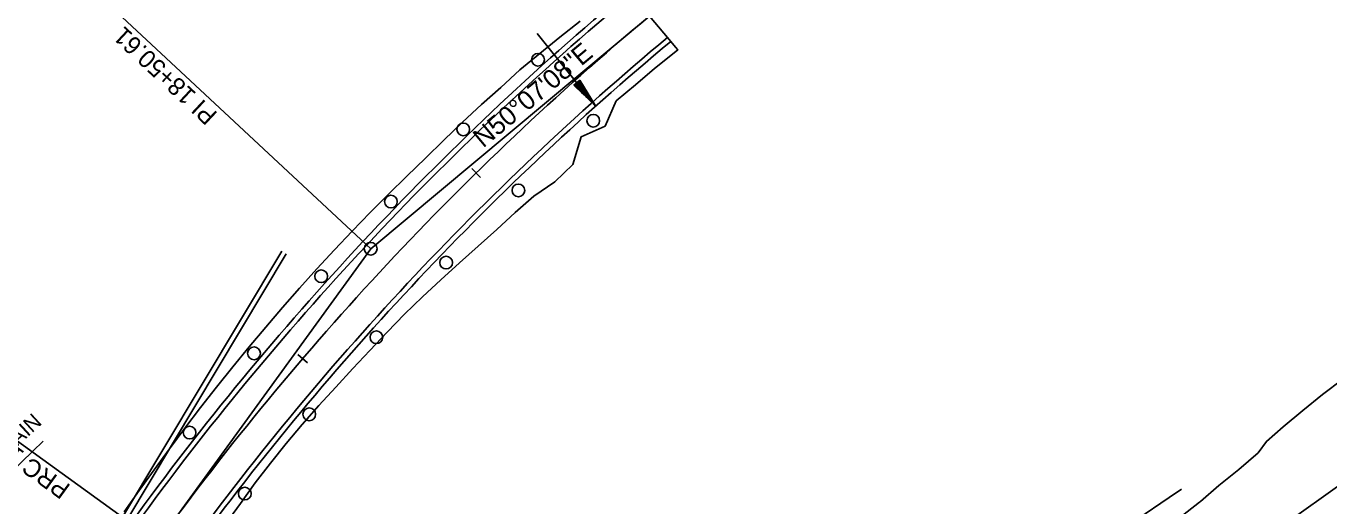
# Model space of a CAD drawing. Extents: x 1300404 to 1323571, y 234004 to 252077.
# Drawn here: x 1311569 to 1312081, y 242253 to 242442 of the extents above; entities that cross this region are included whole.
import ezdxf

# ---------------------------------------------------------------- set-up
doc = ezdxf.new("R2010")
doc.units = 0
for name, color, linetype in [('R_Const Limits', 7, 'Continuous'), ('R_Flow Arrows', 7, 'Continuous'), ('R_MOT Proposed', 7, 'Continuous'), ('R_No Plot', 7, 'Continuous'), ('R_Shoulder', 7, 'Continuous')]:
    doc.layers.add(name, color=color, linetype=linetype)

msp = doc.modelspace()

# ---------------------------------------------------------------- linework, layer by layer
at = {"layer": 'R_Const Limits'}
for points in [[(1312056.31, 242278.46), (1312056.31, 242278.46), (1312062.86, 242284.21), (1312070.55, 242290.61), (1312078.32, 242296.91), (1312086.32, 242302.96)], [(1312022.18, 242248.4), (1312030.07, 242254.56), (1312030.44, 242254.85), (1312037.66, 242261.15), (1312045.44, 242267.46), (1312053.09, 242273.96), (1312056.31, 242278.46), (1312056.31, 242278.46), (1312056.31, 242278.46)]]:
    msp.add_lwpolyline(points, dxfattribs=at)
at = {"layer": 'R_Flow Arrows'}
for p, q in [((1311786.49, 242420.52), (1311784.14, 242418.59)), ((1311784.14, 242418.59), (1311792.75, 242410.46)), ((1311786.49, 242420.52), (1311792.75, 242410.46))]:
    msp.add_line(p, q, dxfattribs=at)
for points in [[(1311769.83, 242438.85), (1311773.45, 242434.36), (1311792.63, 242410.36)], [(1311784.37, 242418.79), (1311785.86, 242416.97)], [(1311784.61, 242418.98), (1311787.58, 242415.34)], [(1311784.85, 242419.17), (1311788.78, 242414.36), (1311789.3, 242413.71)], [(1311785.08, 242419.36), (1311789.01, 242414.55), (1311791.02, 242412.08)], [(1311785.55, 242419.75), (1311789.49, 242414.93), (1311791.49, 242412.46)], [(1311785.79, 242419.94), (1311789.72, 242415.13), (1311790.25, 242414.48)], [(1311786.02, 242420.13), (1311789, 242416.49)], [(1311786.26, 242420.33), (1311787.75, 242418.51)], [(1311575.74, 242278.59), (1311571.61, 242274.57), (1311549.5, 242253.23)], [(1312022.88, 242259.6), (1312018.12, 242256.36), (1311992.67, 242239.14)]]:
    msp.add_lwpolyline(points, dxfattribs=at)
at = {"layer": 'R_MOT Proposed'}
for p, q in [((1311704.36, 242354.22), (1311813.89, 242445.75)), ((1311620.62, 242238.62), (1311704.36, 242354.22))]:
    msp.add_line(p, q, dxfattribs=at)
for points in [[(1311704.36, 242354.22), (1311606.74, 242445.31)], [(1311744.07, 242385.85), (1311747.57, 242382.28)], [(1311675.71, 242312.61), (1311679.51, 242309.36)], [(1311620.62, 242238.62), (1311530.42, 242303.96)]]:
    msp.add_lwpolyline(points, dxfattribs=at)
msp.add_circle((1311704.36, 242354.22), 2.5, dxfattribs=at)
msp.add_arc((1312548.65, 241566.39), 1145.92, 129.881, 144.0818, dxfattribs=at)
at = {"layer": 'R_No Plot'}
for p, q in [((1311806.84, 242454.19), (1311820.95, 242437.3)), ((1311606.86, 242248.59), (1311669.48, 242353.32)), ((1311608.53, 242247.49), (1311671.2, 242352.29))]:
    msp.add_line(p, q, dxfattribs=at)
for points in [[(1311607.5, 242250.8), (1311613.37, 242259.09), (1311619.31, 242267.33), (1311625.31, 242275.53), (1311631.38, 242283.68), (1311637.56, 242291.75), (1311643.81, 242299.76), (1311650.14, 242307.72), (1311656.57, 242315.59), (1311663.11, 242323.38), (1311669.73, 242331.09), (1311676.46, 242338.71), (1311683.25, 242346.28), (1311690.13, 242353.76), (1311697.09, 242361.18), (1311704.2, 242368.44), (1311711.36, 242375.65), (1311718.58, 242382.81), (1311725.84, 242389.91), (1311733.14, 242396.98), (1311740.49, 242403.99), (1311747.9, 242410.93), (1311755.52, 242417.65), (1311762.97, 242424.56), (1311770.82, 242431), (1311778.71, 242437.41), (1311786.63, 242443.76)], [(1311813.89, 242445.75), (1311820.95, 242437.3), (1311822.23, 242435.77), (1311824.11, 242433.52), (1311825, 242432.46), (1311823.55, 242431.29), (1311815.92, 242425.06), (1311808.4, 242418.69), (1311800.83, 242412.38), (1311796.48, 242402.49), (1311787.05, 242398.25), (1311783.79, 242387.32), (1311776.72, 242380.54), (1311768.51, 242374.95), (1311761.16, 242368.44), (1311753.91, 242361.82), (1311746.55, 242355.3), (1311739.24, 242348.71), (1311731.97, 242342.06), (1311724.76, 242335.34), (1311717.69, 242328.49), (1311710.85, 242321.4), (1311704.09, 242314.25), (1311697.35, 242307.06), (1311690.66, 242299.83), (1311684.02, 242292.54), (1311677.49, 242285.15), (1311671.19, 242277.57), (1311664.95, 242269.94), (1311658.94, 242262.13), (1311653.26, 242254.06), (1311647.4, 242246.14)]]:
    msp.add_lwpolyline(points, dxfattribs=at)
for centre in [(1311770.1, 242428.57), (1311791.79, 242404.59), (1311740.73, 242401.16), (1311762.42, 242377.18), (1311712.32, 242372.76), (1311734.02, 242348.77), (1311684.91, 242343.39), (1311706.61, 242319.4), (1311658.53, 242313.09), (1311680.23, 242289.1), (1311633.21, 242281.9), (1311654.91, 242257.91)]:
    msp.add_circle(centre, 2.5, dxfattribs=at)
for radius in [1158.92, 1156.92, 1134.92, 1132.92]:
    msp.add_arc((1312548.65, 241566.39), radius, 129.881, 144.0818, dxfattribs=at)
at = {"layer": 'R_Shoulder'}
msp.add_line((1311862.49, 242102.8), (1312294.82, 242410.7), dxfattribs=at)

# ---------------------------------------------------------------- texts
at = {"layer": 'R_Flow Arrows'}
msp.add_text('GRADE TO DRAIN', height=6, rotation=42.5319, dxfattribs=at).set_placement((1311524.63, 242238.79))
at = {"layer": 'R_MOT Proposed'}
for s, height, rotation, p in [('PI 18+50.61', 7, 136.9814, (1311644.56, 242407.44)), ('N50%%d07\'08"E', 7.5, 39.881, (1311748.55, 242393.65)), ('PRC 17+07.87', 7, 144.0818, (1311586.83, 242260.99))]:
    msp.add_text(s, height=height, rotation=rotation, dxfattribs=at).set_placement(p)

doc.saveas('drawing.dxf')
